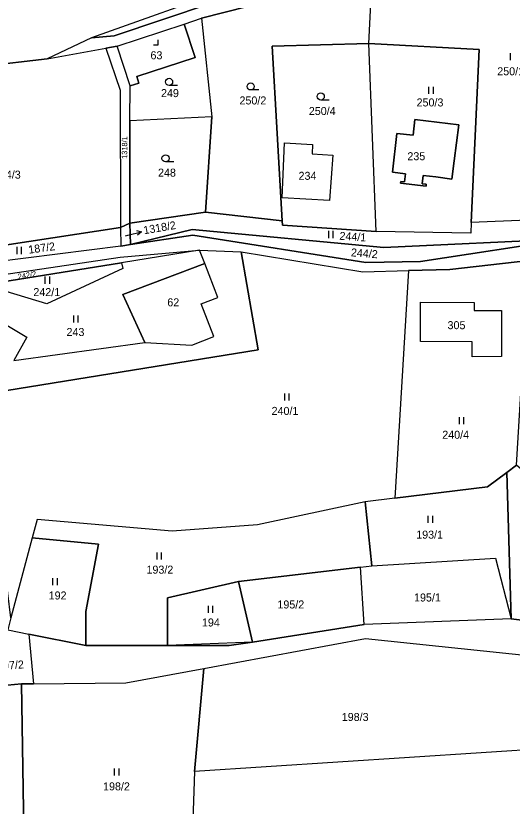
# Model space of a CAD drawing. Extents: x -588699 to -585793, y -1060280 to -1056731.
# Drawn here: x -587926.2 to -587820.9, y -1058283.1 to -1058115.3 of the extents above; entities that cross this region are included whole.
import ezdxf

# ---------------------------------------------------------------- set-up
doc = ezdxf.new("R2010")
doc.units = 0
for name, color, linetype in [('Druh pozemku', 7, 'Continuous'), ('Lesy', 7, 'Continuous'), ('Parcela nároku', 7, 'Continuous'), ('Parcelní číslo', 7, 'Continuous')]:
    doc.layers.add(name, color=color, linetype=linetype)

msp = doc.modelspace()

# ---------------------------------------------------------------- linework, layer by layer
at = {"layer": 'Druh pozemku'}
for p, q in [((-587821.36, -1058123.21), (-587821.36, -1058124.71)), ((-587891.98, -1058130.07), (-587893.73, -1058130.07)), ((-587838.69, -1058130.35), (-587838.69, -1058131.85)), ((-587837.67, -1058131.85), (-587837.67, -1058130.35)), ((-587874.67, -1058131.05), (-587876.42, -1058131.05)), ((-587859.8, -1058133.18), (-587861.55, -1058133.18)), ((-587892.74, -1058146.31), (-587894.49, -1058146.31)), ((-587859.95, -1058160.98), (-587859.95, -1058162.48)), ((-587858.93, -1058162.48), (-587858.93, -1058160.98)), ((-587926.05, -1058164.38), (-587926.05, -1058165.88)), ((-587925.03, -1058165.88), (-587925.03, -1058164.38)), ((-587920.07, -1058170.67), (-587920.07, -1058172.17)), ((-587919.05, -1058172.17), (-587919.05, -1058170.67)), ((-587914.02, -1058178.91), (-587914.02, -1058180.41)), ((-587912.99, -1058180.41), (-587912.99, -1058178.91)), ((-587869.26, -1058195.47), (-587869.26, -1058196.97)), ((-587868.23, -1058196.97), (-587868.23, -1058195.47)), ((-587832.19, -1058200.5), (-587832.19, -1058202)), ((-587831.17, -1058202), (-587831.17, -1058200.5)), ((-587838.81, -1058221.42), (-587838.81, -1058222.92)), ((-587837.79, -1058222.92), (-587837.79, -1058221.42)), ((-587896.35, -1058229.23), (-587896.35, -1058230.73)), ((-587895.33, -1058230.73), (-587895.33, -1058229.23)), ((-587918.46, -1058234.68), (-587918.46, -1058236.18)), ((-587917.44, -1058236.18), (-587917.44, -1058234.68)), ((-587885.45, -1058240.54), (-587885.45, -1058242.04)), ((-587884.43, -1058242.04), (-587884.43, -1058240.54)), ((-587905.38, -1058275.09), (-587905.38, -1058276.59)), ((-587904.35, -1058276.59), (-587904.35, -1058275.09))]:
    msp.add_line(p, q, dxfattribs=at)
msp.add_lwpolyline([(-587897.02, -1058121.43), (-587896.02, -1058121.43), (-587896.02, -1058120.43)], dxfattribs=at)
for centre in [(-587893.73, -1058129.32), (-587876.42, -1058130.3), (-587861.55, -1058132.43), (-587894.49, -1058145.56)]:
    msp.add_circle(centre, 0.75, dxfattribs=at)
at = {"layer": 'Lesy'}
for p, q in [((-587852.32, -1058244.52), (-587876.07, -1058248.24)), ((-587821.15, -1058243.34), (-587852.32, -1058244.52)), ((-587818.31, -1058243.66), (-587821.15, -1058243.34)), ((-587911.37, -1058248.97), (-587923.51, -1058246.54)), ((-587923.51, -1058246.54), (-587922.52, -1058257.09)), ((-587876.07, -1058248.24), (-587894.06, -1058248.99)), ((-587894.06, -1058248.99), (-587911.37, -1058248.97)), ((-587922.52, -1058257.09), (-587925.02, -1058257.11)), ((-587925.02, -1058257.11), (-587924.44, -1058297.23))]:
    msp.add_line(p, q, dxfattribs=at)
at = {"layer": 'Parcela nároku'}
for points in [[(-587850.57, -1058105.64), (-587829.03, -1058099.08), (-587815.92, -1058098.95), (-587814.88, -1058124.25), (-587817.73, -1058158.68), (-587829.62, -1058159.17), (-587827.97, -1058122.42), (-587851.39, -1058121.17)], [(-587829.03, -1058099.08), (-587838.98, -1058099.18), (-587861.9, -1058106.68), (-587884.72, -1058112.59), (-587905.41, -1058119.52), (-587910.22, -1058119.99), (-587919.57, -1058124.47), (-587907.12, -1058122.2), (-587904.74, -1058121.73), (-587890.55, -1058117.09), (-587886.86, -1058115.78), (-587862.63, -1058109.57), (-587850.57, -1058105.64)], [(-587879.59, -1058109.01), (-587910.22, -1058119.99), (-587905.41, -1058119.52), (-587884.72, -1058112.59), (-587861.9, -1058106.68), (-587838.98, -1058099.18), (-587845.09, -1058099.24)], [(-587869.72, -1058158.8), (-587871.89, -1058121.72), (-587851.39, -1058121.17), (-587850.57, -1058105.64), (-587862.63, -1058109.57), (-587886.86, -1058115.78), (-587884.63, -1058136.73), (-587886.03, -1058156.97)], [(-587886.86, -1058115.78), (-587884.63, -1058136.73), (-587902.06, -1058137.63), (-587901.97, -1058130.2), (-587900.15, -1058129.6), (-587900.61, -1058128.21), (-587888.22, -1058124.16), (-587890.55, -1058117.09)], [(-587904.74, -1058121.73), (-587890.55, -1058117.09), (-587888.22, -1058124.16), (-587900.61, -1058128.21), (-587900.15, -1058129.6), (-587901.97, -1058130.2)], [(-587901.97, -1058130.2), (-587904.74, -1058121.73), (-587907.12, -1058122.2), (-587904.13, -1058131.1), (-587904.02, -1058160.23), (-587902.06, -1058159.35), (-587902.06, -1058137.63)], [(-587851.39, -1058121.17), (-587871.89, -1058121.72), (-587869.72, -1058158.8), (-587869.67, -1058159.74), (-587849.78, -1058161.08)], [(-587851.39, -1058121.17), (-587827.97, -1058122.42), (-587829.62, -1058159.17), (-587829.72, -1058161.43), (-587849.78, -1058161.08)], [(-587884.63, -1058136.73), (-587902.06, -1058137.63), (-587902.06, -1058159.35), (-587886.03, -1058156.97)], [(-587841.97, -1058140.67), (-587841.58, -1058137.33), (-587832.29, -1058138.42), (-587833.26, -1058146.12), (-587833.73, -1058149.96), (-587837.14, -1058149.5), (-587839.81, -1058149.22), (-587840.01, -1058150.98), (-587839.22, -1058151.06), (-587839.23, -1058151.44), (-587844.61, -1058150.86), (-587844.56, -1058150.46), (-587843.78, -1058150.55), (-587843.58, -1058148.82), (-587846.32, -1058148.53), (-587845.43, -1058140.3)], [(-587840.01, -1058150.98), (-587839.81, -1058149.22), (-587837.14, -1058149.5), (-587833.73, -1058149.96), (-587833.26, -1058146.12), (-587832.29, -1058138.42), (-587841.58, -1058137.33), (-587841.97, -1058140.67), (-587845.43, -1058140.3), (-587846.32, -1058148.53), (-587843.58, -1058148.82), (-587843.78, -1058150.55), (-587844.56, -1058150.46), (-587844.61, -1058150.86), (-587839.23, -1058151.44), (-587839.22, -1058151.06)], [(-587863.41, -1058144.62), (-587859.02, -1058144.88), (-587859.7, -1058154.53), (-587869.73, -1058153.95), (-587869.25, -1058142.29), (-587863.29, -1058142.64)], [(-587859.7, -1058154.53), (-587869.73, -1058153.95), (-587869.25, -1058142.29), (-587863.29, -1058142.64), (-587863.41, -1058144.62), (-587859.02, -1058144.88)], [(-587808.26, -1058157.99), (-587817.73, -1058158.68), (-587829.62, -1058159.17), (-587829.72, -1058161.43), (-587849.78, -1058161.08), (-587869.67, -1058159.74), (-587869.72, -1058158.8), (-587886.03, -1058156.97), (-587902.06, -1058159.35), (-587901.92, -1058163.88), (-587888.85, -1058160.69), (-587848.18, -1058164.46), (-587808.9, -1058162.63)], [(-587901.92, -1058163.88), (-587902.06, -1058159.35), (-587904.02, -1058160.23), (-587904, -1058164.19)], [(-587937.93, -1058165.4), (-587904.02, -1058160.23), (-587904, -1058164.19), (-587937.63, -1058168.42), (-587939.12, -1058166.7), (-587938.04, -1058166.53), (-587938.13, -1058165.42)], [(-587888.85, -1058160.69), (-587901.92, -1058163.88), (-587888.68, -1058161.9), (-587852.03, -1058167.69), (-587840.39, -1058167.44), (-587808.9, -1058162.63), (-587848.18, -1058164.46)], [(-587937.19, -1058175.57), (-587923.93, -1058183.49), (-587926.7, -1058188.48), (-587898.86, -1058184.66), (-587888.94, -1058185.21), (-587884.21, -1058183.4), (-587886.93, -1058176.48), (-587883.4, -1058175.08), (-587886.16, -1058167.86), (-587887.26, -1058165.09), (-587878.46, -1058165.39), (-587874.84, -1058186.24), (-587933.04, -1058195.62), (-587930.55, -1058216.22), (-587939.22, -1058213.03), (-587944.64, -1058202.99)], [(-587887.26, -1058165.09), (-587903.82, -1058167.75), (-587903.56, -1058168.92), (-587919.66, -1058176.42), (-587933.02, -1058172.44), (-587936.49, -1058173), (-587937.19, -1058175.57), (-587923.93, -1058183.49), (-587926.7, -1058188.48), (-587898.86, -1058184.66), (-587903.56, -1058174.48), (-587886.16, -1058167.86)], [(-587936.03, -1058171.3), (-587904.1, -1058166.51), (-587887.26, -1058165.09), (-587903.82, -1058167.75), (-587933.02, -1058172.44), (-587936.49, -1058173)], [(-587878.46, -1058165.39), (-587852.6, -1058169.68), (-587842.96, -1058169.39), (-587845.87, -1058217.7), (-587852.17, -1058218.46), (-587874.99, -1058223.36), (-587893.08, -1058224.69), (-587921.7, -1058222.21), (-587922.75, -1058226.1), (-587927.3, -1058243.08), (-587929.2, -1058227.37), (-587930.55, -1058216.22), (-587933.04, -1058195.62), (-587874.84, -1058186.24)], [(-587903.82, -1058167.75), (-587903.56, -1058168.92), (-587919.66, -1058176.42), (-587933.02, -1058172.44)], [(-587834.19, -1058169.13), (-587842.96, -1058169.39), (-587845.87, -1058217.7), (-587826.15, -1058215.31), (-587822.07, -1058212.23), (-587820.04, -1058210.7), (-587817.41, -1058167.23)], [(-587886.16, -1058167.86), (-587903.56, -1058174.48), (-587898.86, -1058184.66), (-587888.94, -1058185.21), (-587884.21, -1058183.4), (-587886.93, -1058176.48), (-587883.4, -1058175.08)], [(-587829.44, -1058184.48), (-587840.42, -1058184.47), (-587840.4, -1058176.12), (-587829, -1058176.14), (-587829, -1058177.86), (-587823.19, -1058177.87), (-587823.21, -1058187.64), (-587829.43, -1058187.7)], [(-587829, -1058177.86), (-587823.19, -1058177.87), (-587823.21, -1058187.64), (-587829.43, -1058187.7), (-587829.44, -1058184.48), (-587840.42, -1058184.47), (-587840.4, -1058176.12), (-587829, -1058176.14)], [(-587782.05, -1058211.71), (-587785.66, -1058210.74), (-587807.31, -1058208.75), (-587808.84, -1058212.5), (-587818.5, -1058212.03), (-587820.04, -1058210.7), (-587822.07, -1058212.23), (-587821.15, -1058243.34), (-587818.31, -1058243.66), (-587818.31, -1058231.95), (-587809.37, -1058232.33), (-587801.84, -1058231.28), (-587784.43, -1058228.44)], [(-587845.87, -1058217.7), (-587852.17, -1058218.46), (-587850.74, -1058232.1), (-587824.47, -1058230.46), (-587821.15, -1058243.34), (-587822.07, -1058212.23), (-587826.15, -1058215.31)], [(-587893.08, -1058224.69), (-587921.7, -1058222.21), (-587922.75, -1058226.1), (-587908.69, -1058227.46), (-587911.37, -1058241.77), (-587911.37, -1058248.97), (-587894.06, -1058248.99), (-587894.06, -1058238.86), (-587879, -1058235.4), (-587853.14, -1058232.38), (-587850.74, -1058232.1), (-587852.17, -1058218.46), (-587874.99, -1058223.36)], [(-587908.69, -1058227.46), (-587922.75, -1058226.1), (-587927.3, -1058243.08), (-587927.92, -1058245.65), (-587923.51, -1058246.54), (-587911.37, -1058248.97), (-587911.37, -1058241.77)], [(-587850.74, -1058232.1), (-587824.47, -1058230.46), (-587821.15, -1058243.34), (-587852.32, -1058244.52), (-587853.14, -1058232.38)], [(-587853.14, -1058232.38), (-587879, -1058235.4), (-587876.07, -1058248.24), (-587852.32, -1058244.52)], [(-587894.06, -1058238.86), (-587894.06, -1058248.99), (-587881.01, -1058249.01), (-587876.07, -1058248.24), (-587879, -1058235.4)], [(-587927.92, -1058245.65), (-587923.51, -1058246.54), (-587922.52, -1058257.09), (-587925.02, -1058257.11), (-587931.04, -1058257.66), (-587931.54, -1058249.97)], [(-587813.08, -1058263.36), (-587812.29, -1058270.81), (-587888.36, -1058275.75), (-587886.36, -1058253.87), (-587852.04, -1058247.5), (-587816.19, -1058251.23)], [(-587902.91, -1058256.94), (-587886.36, -1058253.87), (-587888.36, -1058275.75), (-587889.04, -1058296.56), (-587924.44, -1058297.23), (-587925.02, -1058257.11), (-587922.52, -1058257.09)], [(-587940.64, -1058258.04), (-587940.48, -1058259.73), (-587935.06, -1058259.21), (-587935.22, -1058257.53), (-587931.04, -1058257.66), (-587925.02, -1058257.11), (-587924.44, -1058297.23), (-587916.71, -1058316.19), (-587936.92, -1058313.67), (-587941.04, -1058292.83), (-587941.51, -1058290), (-587970.94, -1058295.5), (-587975.43, -1058283.23), (-587977.33, -1058268.66), (-587972.37, -1058263.79), (-587963.49, -1058260.08), (-587944.35, -1058258.4)], [(-587812.29, -1058270.81), (-587888.36, -1058275.75), (-587889.04, -1058296.56), (-587883.78, -1058296.46), (-587884.12, -1058325.43), (-587882.85, -1058325.77), (-587861.42, -1058325.37), (-587847.92, -1058320.82), (-587830.54, -1058313.79), (-587820.75, -1058311.88), (-587806.59, -1058308.33), (-587810.86, -1058284.41)]]:
    msp.add_lwpolyline(points, close=True, dxfattribs=at)
for points in [[(-587879.59, -1058109.01), (-587910.22, -1058119.99), (-587919.57, -1058124.47), (-587933.06, -1058125.98), (-587949.07, -1058127.46), (-587960.12, -1058126.1), (-587971.04, -1058124.84), (-587973.98, -1058124.5), (-587981.13, -1058122.84), (-588005.14, -1058122.81), (-588014.09, -1058122.32), (-588016.07, -1058122.34), (-588019.38, -1058122.28), (-588036.18, -1058121.95), (-588047.38, -1058121.73), (-588054.87, -1058121.87), (-588058.28, -1058121.93), (-588062.02, -1058121.79), (-588073.1, -1058121.39), (-588081.23, -1058121.1), (-588115.84, -1058119.95), (-588127.93, -1058119.84), (-588133.87, -1058117.14), (-588172.01, -1058109.5)], [(-587933.06, -1058125.98), (-587919.57, -1058124.47), (-587907.12, -1058122.2), (-587904.13, -1058131.1), (-587904.02, -1058160.23), (-587937.93, -1058165.4)], [(-587808.9, -1058162.63), (-587840.39, -1058167.44), (-587852.03, -1058167.69), (-587888.68, -1058161.9), (-587901.92, -1058163.88), (-587904, -1058164.19), (-587937.63, -1058168.42), (-587947.48, -1058169.39), (-587955.25, -1058172.16), (-587970.19, -1058177.31), (-587973.4, -1058179.35), (-587972.95, -1058181.31), (-587984.15, -1058185.44), (-588001.45, -1058190.08), (-588001.69, -1058188.1), (-588004.73, -1058188.84), (-588023.22, -1058193.36), (-588026.8, -1058194.23), (-588052.9, -1058201.43)], [(-588048.39, -1058205.39), (-588029.03, -1058199.24), (-588026.47, -1058198.42), (-588006.88, -1058193.67), (-587990.55, -1058189.72), (-587985.91, -1058188.6), (-587978.59, -1058185.67), (-587971.86, -1058182.98), (-587968.85, -1058181.77), (-587963.54, -1058179.65), (-587955.95, -1058177.06), (-587953.79, -1058176.32), (-587936.03, -1058171.3), (-587904.1, -1058166.51), (-587887.26, -1058165.09), (-587878.46, -1058165.39), (-587852.6, -1058169.68), (-587842.96, -1058169.39), (-587834.19, -1058169.13), (-587817.41, -1058167.23)], [(-587818.31, -1058243.66), (-587821.15, -1058243.34), (-587852.32, -1058244.52), (-587876.07, -1058248.24), (-587881.01, -1058249.01), (-587894.06, -1058248.99), (-587911.37, -1058248.97), (-587923.51, -1058246.54), (-587922.52, -1058257.09), (-587902.91, -1058256.94), (-587886.36, -1058253.87), (-587852.04, -1058247.5), (-587816.19, -1058251.23)]]:
    msp.add_lwpolyline(points, dxfattribs=at)
at = {"layer": 'Parcelní číslo'}
for p, q in [((-587902.96, -1058161.98), (-587902.5, -1058161.86)), ((-587902.5, -1058161.86), (-587899.59, -1058161.15))]:
    msp.add_line(p, q, dxfattribs=at)
msp.add_lwpolyline([(-587900.67, -1058160.9), (-587899.59, -1058161.15), (-587900.44, -1058161.87)], dxfattribs=at)

# ---------------------------------------------------------------- texts
at = {"layer": 'Parcela nároku'}
for s, height, p in [('63', 1.7, (-587897.68, -1058124.53)), ('250/1', 1.7, (-587824.12, -1058127.93)), ('249', 1.7, (-587895.45, -1058132.56)), ('250/2', 1.7, (-587878.8, -1058134.12)), ('250/3', 1.7, (-587841.23, -1058134.54)), ('250/4', 1.7, (-587864.09, -1058136.36)), ('235', 1.7, (-587843.18, -1058145.96)), ('184/3', 1.7, (-587930.9, -1058149.87)), ('248', 1.7, (-587896.08, -1058149.45)), ('234', 1.7, (-587866.27, -1058150.12)), ('1318/2', 0.1, (-587903.15, -1058161.98)), ('242/1', 1.7, (-587922.53, -1058174.81)), ('62', 1.7, (-587894.11, -1058176.98)), ('243', 1.7, (-587915.49, -1058183.28)), ('240/1', 1.7, (-587871.99, -1058200.03)), ('240/4', 1.7, (-587835.78, -1058205.09)), ('193/1', 1.7, (-587841.31, -1058226.3)), ('193/2', 1.7, (-587898.53, -1058233.73)), ('192', 1.7, (-587919.28, -1058239.21)), ('195/1', 1.7, (-587841.77, -1058239.64)), ('195/2', 1.7, (-587870.75, -1058241.12)), ('194', 1.7, (-587886.76, -1058244.94)), ('198/3', 1.7, (-587857.1, -1058265)), ('198/2', 1.7, (-587907.74, -1058279.74))]:
    msp.add_text(s, height=height, dxfattribs=at).set_placement(p)
for s, height, rotation, p in [('1318/1', 1.14, 89.5942, (-587902.63, -1058145.69)), ('244/1', 1.7, 356.1026, (-587857.64, -1058162.84)), ('187/2', 1.7, 7.7972, (-587923.47, -1058165.81)), ('244/2', 1.7, 355.6214, (-587855.21, -1058166.35)), ('242/2', 1.14, 9.1881, (-587925.73, -1058171.24)), ('305', 1.7, 359.9478, (-587834.66, -1058181.83)), ('197/2', 1.7, 4.1596, (-587930.16, -1058254.24))]:
    msp.add_text(s, height=height, rotation=rotation, dxfattribs=at).set_placement(p)
at = {"layer": 'Parcelní číslo'}
msp.add_text('1318/2', height=1.7, rotation=9.5835, dxfattribs=at).set_placement((-587899.03, -1058161.69))

doc.saveas('drawing.dxf')
